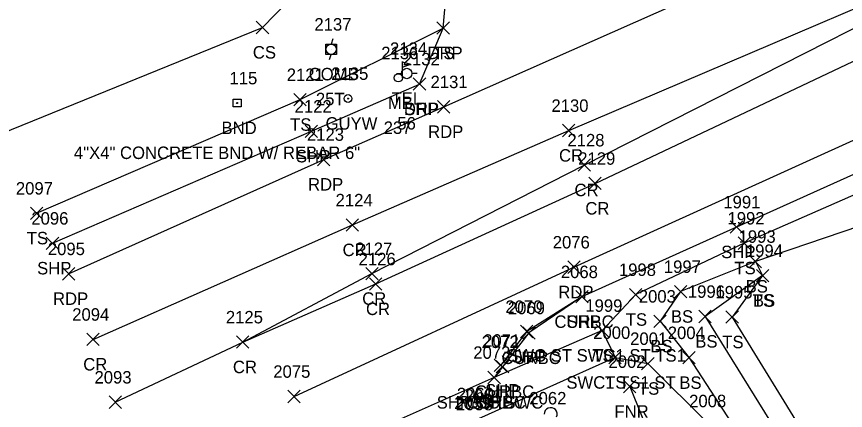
# Model space of a CAD drawing. Extents: x 1477930 to 1480780, y 774090 to 784647.
# Drawn here: x 1478638.5 to 1478771.6, y 774345.7 to 774408.9 of the extents above; entities that cross this region are included whole.
import ezdxf

# ---------------------------------------------------------------- set-up
doc = ezdxf.new("R2010")
doc.units = 0
for name, color, linetype in [('L_A', 7, 'Continuous'), ('L_C', 7, 'Continuous'), ('L_I', 7, 'Continuous'), ('L_TIC', 7, 'Continuous'), ('LELB', 7, 'Continuous'), ('LFNC', 7, 'Continuous'), ('LMB', 7, 'Continuous'), ('LTD', 7, 'Continuous'), ('M_A', 7, 'Continuous'), ('M_C', 7, 'Continuous'), ('M_I', 7, 'Continuous'), ('MHBP', 7, 'Continuous'), ('P_A', 7, 'Continuous'), ('P_I', 7, 'Continuous'), ('P_TIC', 7, 'Continuous'), ('PET', 7, 'Continuous'), ('PRC', 7, 'Continuous'), ('PSP', 7, 'Continuous'), ('R_A', 7, 'Continuous'), ('R_I', 7, 'Continuous'), ('R_TIC', 7, 'Continuous'), ('RC', 7, 'Continuous'), ('RDP', 7, 'Continuous'), ('RSW', 7, 'Continuous'), ('U_A', 7, 'Continuous'), ('U_C', 7, 'Continuous'), ('U_I', 7, 'Continuous'), ('UP', 7, 'Continuous'), ('UPGW', 7, 'Continuous')]:
    doc.layers.add(name, color=color, linetype=linetype)

msp = doc.modelspace()

# ---------------------------------------------------------------- linework, layer by layer
at = {"layer": 'L_TIC'}
for points in [[(1478677.02, 774406.2), (1478679.02, 774408.2)], [(1478679.02, 774406.2), (1478677.02, 774408.2)], [(1478706, 774406.1), (1478708, 774408.1)], [(1478708, 774406.1), (1478706, 774408.1)], [(1478683.03, 774394.6), (1478685.03, 774396.6)], [(1478685.03, 774394.6), (1478683.03, 774396.6)], [(1478640.76, 774376.35), (1478642.76, 774378.35)], [(1478642.76, 774376.35), (1478640.76, 774378.35)], [(1478754.33, 774371.54), (1478756.33, 774373.54)], [(1478756.33, 774371.54), (1478754.33, 774373.54)], [(1478756.11, 774368.6), (1478758.11, 774370.6)], [(1478758.11, 774368.6), (1478756.11, 774370.6)], [(1478756.11, 774368.6), (1478758.11, 774370.6)], [(1478758.11, 774368.6), (1478756.11, 774370.6)], [(1478757.28, 774366.33), (1478759.28, 774368.33)], [(1478759.28, 774366.33), (1478757.28, 774368.33)], [(1478757.28, 774366.33), (1478759.28, 774368.33)], [(1478759.28, 774366.33), (1478757.28, 774368.33)], [(1478736.9, 774363.27), (1478738.9, 774365.27)], [(1478738.9, 774363.27), (1478736.9, 774365.27)], [(1478744.11, 774363.76), (1478746.11, 774365.76)], [(1478746.11, 774363.76), (1478744.11, 774365.76)], [(1478740.82, 774358.99), (1478742.82, 774360.99)], [(1478742.82, 774358.99), (1478740.82, 774360.99)], [(1478748.03, 774359.76), (1478750.03, 774361.76)], [(1478750.03, 774359.76), (1478748.03, 774361.76)], [(1478752.39, 774359.66), (1478754.39, 774361.66)], [(1478754.39, 774359.66), (1478752.39, 774361.66)], [(1478731.52, 774357.51), (1478733.52, 774359.51)], [(1478733.52, 774357.51), (1478731.52, 774359.51)], [(1478733.59, 774353.16), (1478735.59, 774355.16)], [(1478735.59, 774353.16), (1478733.59, 774355.16)], [(1478738.86, 774352.19), (1478740.86, 774354.19)], [(1478740.86, 774352.19), (1478738.86, 774354.19)], [(1478745.47, 774353.13), (1478747.47, 774355.13)], [(1478747.47, 774353.13), (1478745.47, 774355.13)], [(1478735.95, 774348.5), (1478737.95, 774350.5)], [(1478737.95, 774348.5), (1478735.95, 774350.5)]]:
    msp.add_lwpolyline(points, dxfattribs=at)
at = {"layer": 'LELB'}
for points in [[(1478636.03, 774390.1), (1478678.02, 774407.2), (1478696.34, 774426.12), (1478698.64, 774448.38), (1478709.77, 774490.3), (1478718.07, 774514.12), (1478731.48, 774553.42)], [(1478934.45, 774450.58), (1478922.67, 774448.52), (1478891.46, 774434.34), (1478846.59, 774413.31), (1478800.79, 774392.52), (1478755.33, 774372.54), (1478737.9, 774364.27), (1478732.52, 774358.51)], [(1478934.45, 774450.58), (1478925.02, 774444.04), (1478895.86, 774426.81), (1478850.02, 774405.81), (1478804.52, 774385.73), (1478757.11, 774369.6), (1478745.11, 774364.76), (1478741.82, 774359.99), (1478746.47, 774354.13), (1478763.57, 774327.81), (1478779.16, 774285.74)], [(1478641.76, 774377.35), (1478684.03, 774395.6), (1478707, 774407.1)], [(1478757.11, 774369.6), (1478758.28, 774367.33), (1478749.03, 774360.76), (1478768.09, 774330.04), (1478784.18, 774288.09)], [(1478758.28, 774367.33), (1478753.39, 774360.66), (1478771, 774332.01), (1478786.22, 774288.67)], [(1478734.59, 774354.16), (1478739.86, 774353.19), (1478749.89, 774343.18), (1478759.29, 774325.22), (1478771.1, 774282.02)]]:
    msp.add_lwpolyline(points, dxfattribs=at)
at = {"layer": 'LFNC'}
msp.add_lwpolyline([(1478736.95, 774349.5), (1478748.61, 774320.46), (1478764.83, 774279.72)], dxfattribs=at)
at = {"layer": 'LMB'}
for p, q in [((1478700.47, 774401.7), (1478701.77, 774401.32)), ((1478700.48, 774399.11), (1478700.48, 774401.71)), ((1478700.48, 774400.8), (1478701.76, 774401.31)), ((1478699.82, 774399.1), (1478699.82, 774399.1))]:
    msp.add_line(p, q, dxfattribs=at)
msp.add_circle((1478699.82, 774399.1), 0.656, dxfattribs=at)
at = {"layer": 'LTD'}
msp.add_arc((1478724.26, 774345.06), 1.05, 335.5272, 180.9563, dxfattribs=at)
at = {"layer": 'MHBP'}
msp.add_lwpolyline([(1478673.32, 774395.68), (1478674.57, 774395.68), (1478674.57, 774394.43), (1478673.32, 774394.43)], close=True, dxfattribs=at)
msp.add_circle((1478673.94, 774395.06), 0.0833, dxfattribs=at)
at = {"layer": 'P_TIC'}
for points in [[(1478702.21, 774397.11), (1478704.21, 774399.11)], [(1478704.21, 774397.11), (1478702.21, 774399.11)], [(1478706.1, 774393.45), (1478708.1, 774395.45)], [(1478708.1, 774393.45), (1478706.1, 774395.45)], [(1478684.86, 774389.52), (1478686.86, 774391.52)], [(1478686.86, 774389.52), (1478684.86, 774391.52)], [(1478726.16, 774389.64), (1478728.16, 774391.64)], [(1478728.16, 774389.64), (1478726.16, 774391.64)], [(1478686.83, 774384.99), (1478688.83, 774386.99)], [(1478688.83, 774384.99), (1478686.83, 774386.99)], [(1478728.65, 774384.09), (1478730.65, 774386.09)], [(1478730.65, 774384.09), (1478728.65, 774386.09)], [(1478730.38, 774381.14), (1478732.38, 774383.14)], [(1478732.38, 774381.14), (1478730.38, 774383.14)], [(1478691.43, 774374.46), (1478693.43, 774376.46)], [(1478693.43, 774374.46), (1478691.43, 774376.46)], [(1478753.09, 774374.13), (1478755.09, 774376.13)], [(1478755.09, 774374.13), (1478753.09, 774376.13)], [(1478643.3, 774371.52), (1478645.3, 774373.52)], [(1478645.3, 774371.52), (1478643.3, 774373.52)], [(1478645.9, 774366.62), (1478647.9, 774368.62)], [(1478647.9, 774366.62), (1478645.9, 774368.62)], [(1478694.58, 774366.64), (1478696.58, 774368.64)], [(1478696.58, 774366.64), (1478694.58, 774368.64)], [(1478726.99, 774367.69), (1478728.99, 774369.69)], [(1478728.99, 774367.69), (1478726.99, 774369.69)], [(1478695.18, 774364.99), (1478697.18, 774366.99)], [(1478697.18, 774364.99), (1478695.18, 774366.99)], [(1478728.28, 774362.93), (1478730.28, 774364.93)], [(1478730.28, 774362.93), (1478728.28, 774364.93)], [(1478719.41, 774357.34), (1478721.41, 774359.34)], [(1478721.41, 774357.34), (1478719.41, 774359.34)], [(1478649.81, 774356.08), (1478651.81, 774358.08)], [(1478651.81, 774356.08), (1478649.81, 774358.08)], [(1478673.83, 774355.65), (1478675.83, 774357.65)], [(1478675.83, 774355.65), (1478673.83, 774357.65)], [(1478673.83, 774355.65), (1478675.83, 774357.65)], [(1478675.83, 774355.65), (1478673.83, 774357.65)], [(1478715.2, 774351.9), (1478717.2, 774353.9)], [(1478717.2, 774351.9), (1478715.2, 774353.9)], [(1478714.18, 774349.96), (1478716.18, 774351.96)], [(1478716.18, 774349.96), (1478714.18, 774351.96)], [(1478682.07, 774346.91), (1478684.07, 774348.91)], [(1478684.07, 774346.91), (1478682.07, 774348.91)], [(1478653.38, 774345.99), (1478655.38, 774347.99)], [(1478655.38, 774345.99), (1478653.38, 774347.99)]]:
    msp.add_lwpolyline(points, dxfattribs=at)
at = {"layer": 'PET'}
for points in [[(1478646.9, 774367.62), (1478687.83, 774385.99), (1478707.1, 774394.45), (1478751.46, 774414.17), (1478808.39, 774438.04), (1478858.43, 774458.78), (1478902.75, 774477.06), (1478935.49, 774490.35), (1478955.71, 774499.82), (1478999.73, 774519.88), (1479070.74, 774558.33), (1479113.57, 774583.69), (1479168.73, 774620.31), (1479212.4, 774655.38)], [(1478683.07, 774347.91), (1478727.99, 774368.69), (1478775.23, 774390.17), (1478824.48, 774413.21), (1478871.78, 774434.98), (1478928.06, 774460.83), (1478969.71, 774480.29), (1479018.44, 774502.95), (1479067.21, 774527.02), (1479117.77, 774550.82), (1479128.42, 774557.99), (1479157.72, 774572.57), (1479186.74, 774593.83), (1479220.19, 774621.01), (1479234.45, 774632.83)]]:
    msp.add_lwpolyline(points, dxfattribs=at)
at = {"layer": 'PRC'}
for points in [[(1478654.38, 774346.99), (1478674.83, 774356.65), (1478696.18, 774365.99), (1478731.38, 774382.14), (1478814.02, 774421.35), (1478859.83, 774442.03), (1478906.42, 774463.43), (1478938.4, 774478.56), (1479002.95, 774508.43), (1479077.31, 774545.61), (1479120.22, 774569.96), (1479177.27, 774607.59), (1479194.24, 774620.68)], [(1478674.83, 774356.65), (1478695.58, 774367.64), (1478729.65, 774385.09), (1478811.24, 774426.58), (1478858.43, 774445.95), (1478905.31, 774465.16), (1478938.4, 774478.56)], [(1478650.81, 774357.08), (1478692.43, 774375.46), (1478727.16, 774390.64), (1478811.24, 774426.58)]]:
    msp.add_lwpolyline(points, dxfattribs=at)
at = {"layer": 'PSP'}
for points in [[(1478890.7, 774436.75), (1478844.98, 774416.36), (1478799.14, 774395.41), (1478754.09, 774375.13), (1478729.28, 774363.93), (1478720.41, 774358.34), (1478716.2, 774352.9)], [(1478644.3, 774372.52), (1478685.86, 774390.52), (1478703.21, 774398.11)]]:
    msp.add_lwpolyline(points, dxfattribs=at)
at = {"layer": 'R_TIC'}
for points in [[(1478706, 774406.1), (1478708, 774408.1)], [(1478708, 774406.1), (1478706, 774408.1)], [(1478702.21, 774397.11), (1478704.21, 774399.11)], [(1478704.21, 774397.11), (1478702.21, 774399.11)], [(1478728.28, 774362.93), (1478730.28, 774364.93)], [(1478730.28, 774362.93), (1478728.28, 774364.93)], [(1478731.52, 774357.51), (1478733.52, 774359.51)], [(1478733.52, 774357.51), (1478731.52, 774359.51)], [(1478731.52, 774357.51), (1478733.52, 774359.51)], [(1478733.52, 774357.51), (1478731.52, 774359.51)], [(1478719.78, 774357.12), (1478721.78, 774359.12)], [(1478721.78, 774357.12), (1478719.78, 774359.12)], [(1478733.59, 774353.16), (1478735.59, 774355.16)], [(1478735.59, 774353.16), (1478733.59, 774355.16)], [(1478715.52, 774351.69), (1478717.52, 774353.69)], [(1478717.52, 774351.69), (1478715.52, 774353.69)], [(1478714.18, 774349.96), (1478716.18, 774351.96)], [(1478716.18, 774349.96), (1478714.18, 774351.96)], [(1478714.18, 774349.96), (1478716.18, 774351.96)], [(1478716.18, 774349.96), (1478714.18, 774351.96)]]:
    msp.add_lwpolyline(points, dxfattribs=at)
at = {"layer": 'RC'}
msp.add_lwpolyline([(1478729.28, 774363.93), (1478720.78, 774358.12), (1478716.52, 774352.69), (1478715.18, 774350.96)], dxfattribs=at)
at = {"layer": 'RDP'}
msp.add_lwpolyline([(1478703.21, 774398.11), (1478707, 774407.1), (1478709.6, 774436.68), (1478709.28, 774465.3), (1478714.97, 774487.33), (1478730.23, 774512.18), (1478752.1, 774541.74), (1478767.16, 774553.47), (1478789.48, 774563.65), (1478796.27, 774564.29)], dxfattribs=at)
at = {"layer": 'RSW'}
for points in [[(1478732.52, 774358.51), (1478715.18, 774350.96), (1478688.25, 774338.96)], [(1478732.52, 774358.51), (1478734.59, 774354.16), (1478712.68, 774344.31), (1478689.34, 774334.22)]]:
    msp.add_lwpolyline(points, dxfattribs=at)
at = {"layer": 'UP'}
for p, q in [((1478688.2, 774402.86), (1478688.2, 774404.53)), ((1478688.2, 774404.53), (1478689.86, 774404.53)), ((1478689.28, 774405.36), (1478689.03, 774404.53)), ((1478689.86, 774404.53), (1478689.86, 774402.86)), ((1478689.03, 774403.7), (1478689.03, 774403.7)), ((1478689.86, 774402.86), (1478688.2, 774402.86)), ((1478688.78, 774402.03), (1478689.03, 774402.86)), ((1478699.5, 774399.8), (1478700.33, 774399.8)), ((1478701.16, 774399.8), (1478701.16, 774399.8)), ((1478702.83, 774399.8), (1478702, 774399.8)), ((1478702, 774399.8), (1478702, 774399.8)), ((1478702.83, 774399.8), (1478702.83, 774399.8))]:
    msp.add_line(p, q, dxfattribs=at)
for centre in [(1478689.03, 774403.7), (1478701.16, 774399.8)]:
    msp.add_circle(centre, 0.833, dxfattribs=at)
at = {"layer": 'UPGW'}
for radius in [0.625, 0.0833]:
    msp.add_circle((1478691.74, 774395.78), radius, dxfattribs=at)

# ---------------------------------------------------------------- texts
at = {"layer": 'L_A'}
for s, p in [('CS', (1478676.46, 774402.2)), ('TS', (1478705.41, 774402.1)), ('MB', (1478698.13, 774394.1)), ('TS', (1478682.44, 774390.6)), ('TS', (1478640.17, 774372.35)), ('TS', (1478753.74, 774367.54)), ('BS', (1478755.55, 774364.6)), ('BS', (1478755.55, 774364.6)), ('TS', (1478756.69, 774362.33)), ('BS', (1478756.72, 774362.33)), ('TS', (1478736.31, 774359.27)), ('BS', (1478743.56, 774359.76)), ('BS', (1478740.26, 774354.99)), ('BS', (1478747.47, 774355.76)), ('TS', (1478751.8, 774355.66)), ('TS', (1478730.93, 774353.51)), ('TS', (1478732.99, 774349.16)), ('TS', (1478738.27, 774348.19)), ('BS', (1478744.91, 774349.13)), ('FNR', (1478734.49, 774344.5))]:
    msp.add_text(s, height=2, dxfattribs=at).set_placement(p)
at = {"layer": 'L_C'}
msp.add_text('237', height=2, dxfattribs=at).set_placement((1478697.46, 774390.1))
at = {"layer": 'L_I'}
for s, p in [('2136', (1478697.07, 774402.1)), ('2121', (1478681.9, 774398.6)), ('2097', (1478638.43, 774380.35)), ('1992', (1478752.64, 774375.54)), ('1993', (1478754.42, 774372.6)), ('1993', (1478754.42, 774372.6)), ('1994', (1478755.59, 774370.33)), ('1994', (1478755.59, 774370.33)), ('1998', (1478735.21, 774367.27)), ('1997', (1478742.42, 774367.76)), ('2003', (1478738.4, 774362.99)), ('1996', (1478746.28, 774363.76)), ('1995', (1478750.7, 774363.66)), ('1999', (1478729.82, 774361.51)), ('2000', (1478731.08, 774357.16)), ('2001', (1478737.01, 774356.19)), ('2004', (1478743.05, 774357.13)), ('2002', (1478733.54, 774352.5)), ('2062', (1478720.83, 774346.63)), ('2008', (1478746.48, 774346.18))]:
    msp.add_text(s, height=2, dxfattribs=at).set_placement(p)
at = {"layer": 'M_A'}
msp.add_text('BND', height=2, dxfattribs=at).set_placement((1478671.43, 774390.06))
at = {"layer": 'M_C'}
msp.add_text('4"X4" CONCRETE BND W/ REBAR 6"', height=2, dxfattribs=at).set_placement((1478647.74, 774386.06))
at = {"layer": 'M_I'}
msp.add_text('115', height=2, dxfattribs=at).set_placement((1478672.71, 774398.06))
at = {"layer": 'P_A'}
for s, p in [('SHP', (1478700.75, 774393.11)), ('RDP', (1478704.59, 774389.45)), ('SHP', (1478683.39, 774385.52)), ('CR', (1478725.6, 774385.64)), ('RDP', (1478685.32, 774380.99)), ('CR', (1478728.08, 774380.09)), ('CR', (1478729.82, 774377.14)), ('CR', (1478690.86, 774370.46)), ('SHP', (1478751.63, 774370.13)), ('SHP', (1478641.84, 774367.52)), ('RDP', (1478644.39, 774362.62)), ('CR', (1478694.01, 774362.64)), ('RDP', (1478725.48, 774363.69)), ('CR', (1478694.62, 774360.99)), ('SHP', (1478726.81, 774358.93)), ('SHP', (1478717.95, 774353.34)), ('CR', (1478649.24, 774352.08)), ('CR', (1478673.26, 774351.65)), ('CR', (1478673.26, 774351.65)), ('SHP', (1478713.74, 774347.9)), ('SHP', (1478712.71, 774345.96))]:
    msp.add_text(s, height=2, dxfattribs=at).set_placement(p)
at = {"layer": 'P_I'}
for s, p in [('2132', (1478700.52, 774401.11)), ('2131', (1478704.98, 774397.45)), ('2122', (1478683.17, 774393.52)), ('2130', (1478724.38, 774393.64)), ('2123', (1478685.14, 774388.99)), ('2128', (1478726.95, 774388.09)), ('2129', (1478728.68, 774385.14)), ('2124', (1478689.74, 774378.46)), ('1991', (1478751.97, 774378.13)), ('2096', (1478640.91, 774375.52)), ('2095', (1478643.56, 774370.62)), ('2127', (1478692.89, 774370.64)), ('2076', (1478724.59, 774371.69)), ('2126', (1478693.44, 774368.99)), ('2068', (1478725.89, 774366.93)), ('2070', (1478716.99, 774361.34)), ('2094', (1478647.47, 774360.08)), ('2125', (1478672.13, 774359.65)), ('2125', (1478672.13, 774359.65)), ('2071', (1478713.43, 774355.9)), ('2073', (1478711.84, 774353.96)), ('2075', (1478679.74, 774350.91)), ('2093', (1478651.05, 774349.99))]:
    msp.add_text(s, height=2, dxfattribs=at).set_placement(p)
at = {"layer": 'R_A'}
for s, p in [('DRP', (1478704.48, 774402.1)), ('DRP', (1478700.7, 774393.11)), ('CURBC', (1478724.86, 774358.93)), ('SWC ST SWC1 ST TS1', (1478717.28, 774353.51)), ('SWC ST SWC1 ST TS1', (1478717.28, 774353.51)), ('CURBC', (1478716.37, 774353.12)), ('SWC1 TS1 ST', (1478726.78, 774349.16)), ('CURBC', (1478712.11, 774347.69)), ('SHP CC SWC', (1478705.97, 774345.96)), ('CURBC', (1478710.76, 774345.96))]:
    msp.add_text(s, height=2, dxfattribs=at).set_placement(p)
at = {"layer": 'R_I'}
for s, p in [('2132', (1478700.52, 774401.11)), ('2068', (1478725.89, 774366.93)), ('1999', (1478729.82, 774361.51)), ('1999', (1478729.82, 774361.51)), ('2069', (1478717.39, 774361.12)), ('2000', (1478731.08, 774357.16)), ('2072', (1478713.18, 774355.69)), ('2073', (1478711.84, 774353.96)), ('2073', (1478711.84, 774353.96)), ('2060', (1478709.2, 774347.31)), ('2060', (1478709.2, 774347.31)), ('2060', (1478709.2, 774347.31)), ('2061', (1478710.47, 774347.07)), ('2059', (1478708.78, 774345.88)), ('2058', (1478709.05, 774345.69))]:
    msp.add_text(s, height=2, dxfattribs=at).set_placement(p)
at = {"layer": 'U_A'}
for s, p in [('COMB', (1478685.42, 774398.7)), ('TEL', (1478698.72, 774394.8)), ('GUYW', (1478688.13, 774390.78))]:
    msp.add_text(s, height=2, dxfattribs=at).set_placement(p)
at = {"layer": 'U_C'}
for s, p in [('25T', (1478686.58, 774394.7)), ('56', (1478699.64, 774390.8))]:
    msp.add_text(s, height=2, dxfattribs=at).set_placement(p)
at = {"layer": 'U_I'}
for s, p in [('2137', (1478686.34, 774406.7)), ('2134', (1478698.47, 774402.8)), ('2135', (1478689.04, 774398.78)), ('2008', (1478746.48, 774346.18))]:
    msp.add_text(s, height=2, dxfattribs=at).set_placement(p)

doc.saveas('drawing.dxf')
